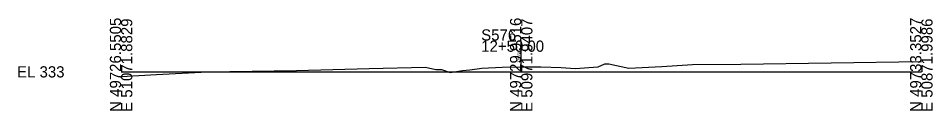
# Model space of a CAD drawing. Extents: x 7499 to 9928, y 92844 to 95367.
# Drawn here: x 7499.3 to 7727.8, y 95343.9 to 95366.9 of the extents above; entities that cross this region are included whole.
import ezdxf

# ---------------------------------------------------------------- set-up
doc = ezdxf.new("R2010")
doc.units = 0
for name, color, linetype in [('Level 10', 7, 'Continuous'), ('Level 60', 7, 'Continuous'), ('Level 63', 7, 'Continuous')]:
    doc.layers.add(name, color=color, linetype=linetype)

msp = doc.modelspace()

# ---------------------------------------------------------------- linework, layer by layer
at = {"layer": 'Level 60'}
for p, q in [((7679.9, 95355.47), (7724.99, 95356.16)), ((7546.59, 95353.54), (7568.8, 95353.86)), ((7568.8, 95353.86), (7586.95, 95354.36)), ((7586.95, 95354.36), (7601.07, 95354.69)), ((7601.07, 95354.69), (7603.69, 95354.11)), ((7603.69, 95354.11), (7605.06, 95354.11)), ((7605.06, 95354.11), (7607.27, 95353.37)), ((7607.27, 95353.37), (7610.34, 95353.85)), ((7610.34, 95353.85), (7612.17, 95354.07)), ((7612.17, 95354.07), (7615.19, 95354.46)), ((7615.19, 95354.46), (7620.24, 95354.68)), ((7620.24, 95354.68), (7625.06, 95354.84)), ((7625.06, 95354.84), (7629.91, 95354.8)), ((7629.91, 95354.8), (7635.01, 95354.67)), ((7635.01, 95354.67), (7638.47, 95354.42)), ((7638.47, 95354.42), (7644.19, 95354.77)), ((7644.19, 95354.77), (7645.89, 95355.52)), ((7645.89, 95355.52), (7646.88, 95355.52)), ((7646.88, 95355.52), (7651.91, 95354.44)), ((7651.91, 95354.44), (7660.17, 95354.88)), ((7660.17, 95354.88), (7667.8, 95355.39)), ((7667.8, 95355.39), (7679.9, 95355.47)), ((7524.99, 95352.4), (7533.8, 95352.88)), ((7533.8, 95352.88), (7546.59, 95353.54))]:
    msp.add_line(p, q, dxfattribs=at)
at = {"layer": 'Level 63'}
for p, q in [((7624.99, 95353.55), (7624.99, 95361.37)), ((7524.99, 95353.55), (7624.99, 95353.55)), ((7624.99, 95353.55), (7724.99, 95353.55))]:
    msp.add_line(p, q, dxfattribs=at)

# ---------------------------------------------------------------- texts
at = {"layer": 'Level 10'}
msp.add_text('334.29', height=0.6, rotation=90, dxfattribs=at).set_placement((7624.59, 95355.84))
at = {"layer": 'Level 63'}
for s, p in [('N 49726.5505', (7524.99, 95343.55)), ('E 51071.8829', (7527.79, 95343.55)), ('N 49729.9516', (7624.99, 95343.55)), ('E 50971.9407', (7627.79, 95343.55)), ('N 49733.3527', (7724.99, 95343.55)), ('E 50871.9986', (7727.79, 95343.55))]:
    msp.add_text(s, height=2.8, rotation=90, dxfattribs=at).set_placement(p)
for s, p in [('S576', (7614.99, 95361.37)), ('12+50.00', (7614.99, 95358.57)), ('EL 333', (7498.99, 95352.15))]:
    msp.add_text(s, height=2.8, dxfattribs=at).set_placement(p)

doc.saveas('drawing.dxf')
